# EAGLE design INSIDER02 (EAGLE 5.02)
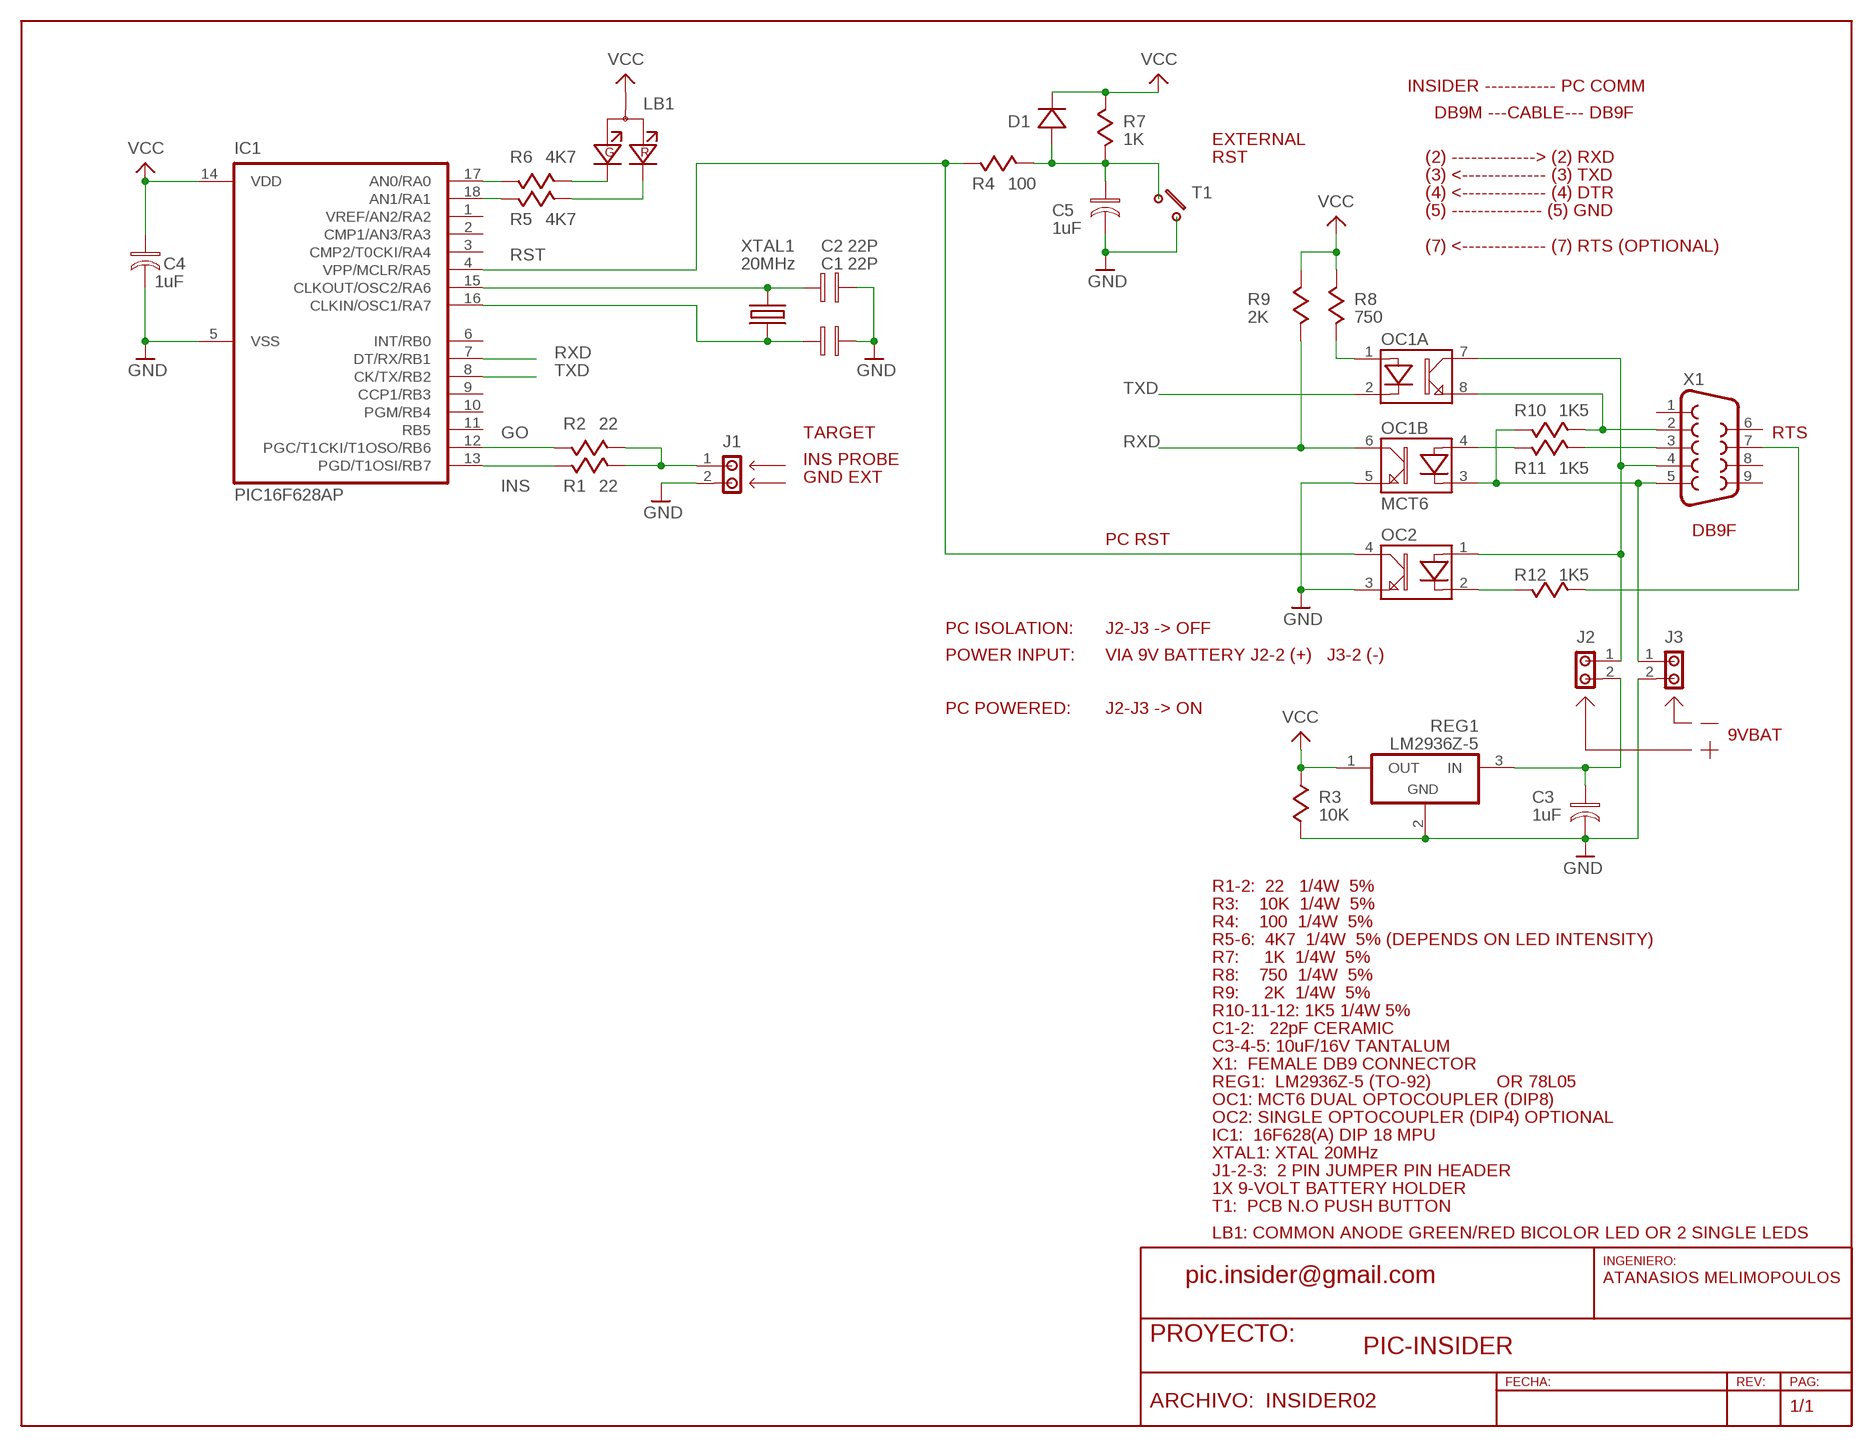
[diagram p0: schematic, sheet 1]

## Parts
C1  22P  CAP02  [C02]
C2  22P  CAP02  [C02]
C3  1uF  CAPE01  [CP01]
C4  1uF  CAPE01  [CP01]
C5  1uF  CAPE01  [CP01]
D1  1N4148  DIODE03  [D03]
IC1  PIC16F628AP  [DIL18]
J1  JMP2  [JP2]
J2  JMP2  [JP2]
J3  JMP2  [JP2]
LB1  LEDBIAC  [LEDBAC]
OC1  MCT6  OPTO2G  [DIL08]
OC2  OPTO1A  [DIL04]
R1  22  RES03  [R03]
R2  22  RES03  [R03]
R3  10K  RES03  [R03]
R4  100  RES03  [R03]
R5  4K7  RES03  [R03]
R6  4K7  RES03  [R03]
R7  1K  RES03  [R03]
R8  750  RES03  [R03]
R9  2K  RES03  [R03]
R10  1K5  RES03  [R03]
R11  1K5  RES03  [R03]
R12  1K5  RES03  [R03]
REG1  LM2936Z-5  78XXL  [TO92A]
T1  TEC3  [TEC3L]
X1  F09D  [F09D]
XTAL1  20MHz  XTALV300  [HC49V]

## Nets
GND: C1.P$2 C2.P$2 C3.P$2 C4.P$2 C5.P$2 IC1.5(VSS) J1.2 J3.2 OC1.5(B:E) OC2.3(E) R3.P$2 REG1.2(GND) T1.1
GO: IC1.12(PGC/T1CKI/T1OSO/RB6) R2.P$2
INS: IC1.13(PGD/T1OSI/RB7) R1.P$1
N$1: J3.1 OC1.3(B:K) R10.P$1 X1.5
N$2: OC1.8(A:E) R10.P$2 X1.2
N$3: J2.1 OC1.7(A:C) OC2.1(A) X1.4
N$4: R11.P$2 X1.3
N$5: OC1.4(B:A) R11.P$1
N$6: OC1.1(A:A) R8.P$2
N$8: OC2.2(K) R12.P$1
N$9: J1.1 R1.P$2 R2.P$1
N$10: C2.P$1 IC1.15(CLKOUT/OSC2/RA6) XTAL1.1
N$11: C1.P$1 IC1.16(CLKIN/OSC1/RA7) XTAL1.2
N$12: IC1.17(AN0/RA0) R6.P$2
N$14: LB1.G(K2) R6.P$1
N$15: LB1.R(K1) R5.P$1
N$16: IC1.18(AN1/RA1) R5.P$2
N$18: R12.P$2 X1.7
N$19: C5.P$1 D1.P$1(A) R4.P$1 R7.P$2 T1.4
N$20: C3.P$1 J2.2 REG1.3(IN)
RST: IC1.4(VPP/MCLR/RA5) OC2.4(C) R4.P$2
RXD: IC1.7(DT/RX/RB1) OC1.6(B:C) R9.P$2
TXD: IC1.8(CK/TX/RB2) OC1.2(A:K)
VCC: C4.P$1 D1.P$2(K) IC1.14(VDD) LB1.A R3.P$1 R7.P$1 R8.P$1 R9.P$1 REG1.1(OUT)
Unconnected: IC1.1(VREF/AN2/RA2) IC1.2(CMP1/AN3/RA3) IC1.3(CMP2/T0CKI/RA4) IC1.6(INT/RB0) IC1.9(CCP1/RB3) IC1.10(PGM/RB4) IC1.11(RB5) X1.1 X1.6 X1.8 X1.9

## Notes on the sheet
- INSIDER ----------- PC COMM
- DB9M ---CABLE--- DB9F
- EXTERNAL
- RST | (2) -------------> (2) RXD
- (3) <------------- (3) TXD
- (4) <------------- (4) DTR
- (5) -------------- (5) GND
- (7) <------------- (7) RTS (OPTIONAL)
- TARGET | RTS
- INS PROBE
- GND EXT
- DB9F
- PC RST
- PC ISOLATION: | J2-J3 -> OFF
- POWER INPUT: | VIA 9V BATTERY J2-2 (+)   J3-2 (-)
- PC POWERED: | J2-J3 -> ON
- 9VBAT
- R1-2:  22   1/4W  5%
- R3:    10K  1/4W  5%
- R4:    100  1/4W  5%
- R5-6:  4K7  1/4W  5% (DEPENDS ON LED INTENSITY)
- R7:     1K  1/4W  5%
- R8:    750  1/4W  5%
- R9:     2K  1/4W  5%
- R10-11-12: 1K5 1/4W 5%
- C1-2:   22pF CERAMIC
- C3-4-5: 10uF/16V TANTALUM
- X1:  FEMALE DB9 CONNECTOR
- REG1:  LM2936Z-5 (TO-92) | OR 78L05
- OC1: MCT6 DUAL OPTOCOUPLER (DIP8)
- OC2: SINGLE OPTOCOUPLER (DIP4) OPTIONAL
- IC1:  16F628(A) DIP 18 MPU
- XTAL1: XTAL 20MHz
- J1-2-3:  2 PIN JUMPER PIN HEADER
- 1X 9-VOLT BATTERY HOLDER
- T1:  PCB N.O PUSH BUTTON
- LB1: COMMON ANODE GREEN/RED BICOLOR LED OR 2 SINGLE LEDS
- pic.insider@gmail.com | ATANASIOS MELIMOPOULOS
- PIC-INSIDER

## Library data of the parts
C1 C2 = AtaLib:CAP: Capacitor
C3-C5 = AtaLib:CAPE: Capacitor Pol. Elect.
D1 = AtaLib:DIODE: DIODES
IC1 = AtaLib:PIC16F6*: PIC 16F627 - 628 - 648 family
J1-J3 = AtaLib:JMP2: Jumper 2xPin
LB1 = AtaLib:LEDBIAC: LED BIcolor AC 5mm
OC1 = AtaLib:OPTO2G: OPTOCOUPLER dual unit
OC2 = AtaLib:OPTO1A: OPTOCOUPLER simple
R1-R12 = AtaLib:RES: Resistor
REG1 = AtaLib:78XX: Positive Voltage Regulator
T1 = AtaLib:TEC: TECLAS INDIVIDUALES
X1 = AtaLib:F09: D-SUB 9 FEMALE
XTAL1 = AtaLib:XTALV300: Xtal Vert 300 mils

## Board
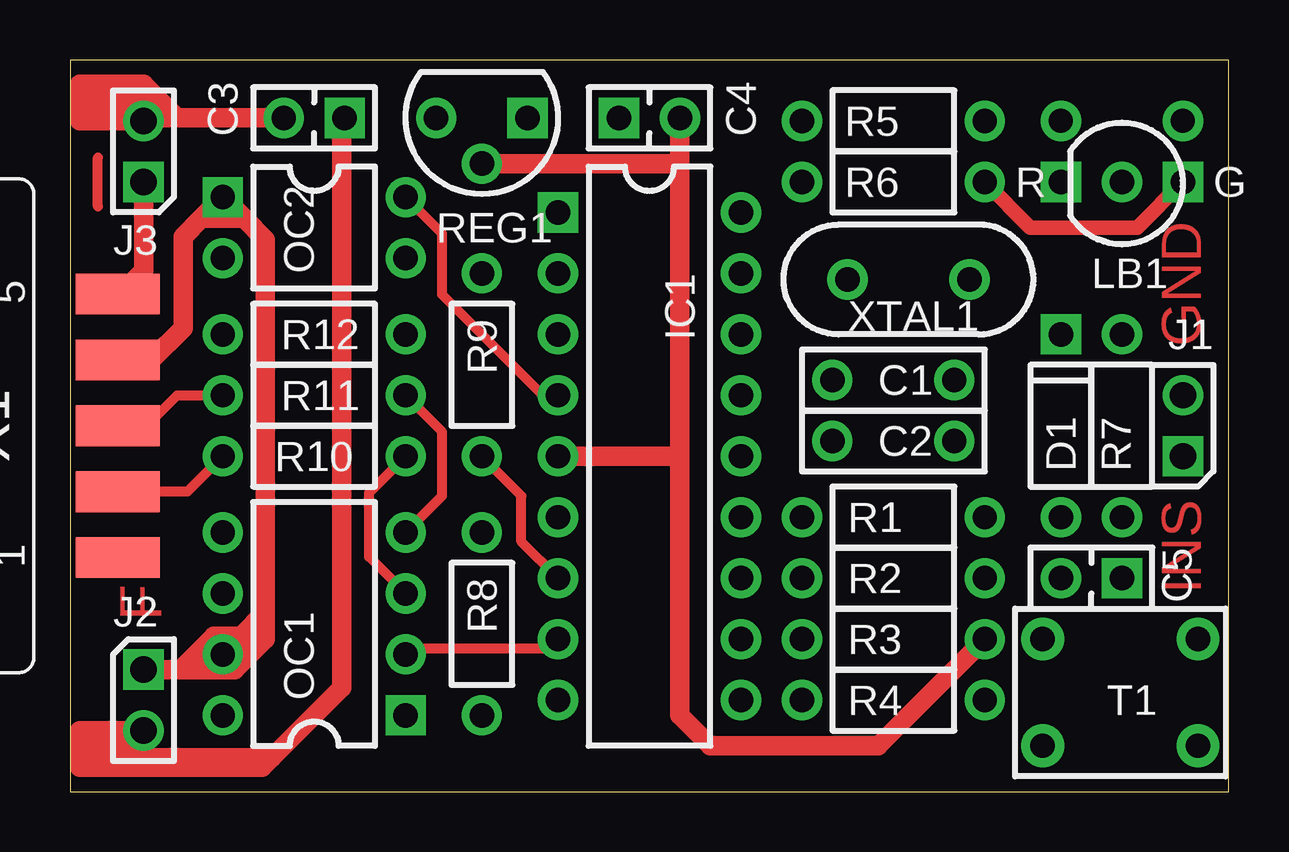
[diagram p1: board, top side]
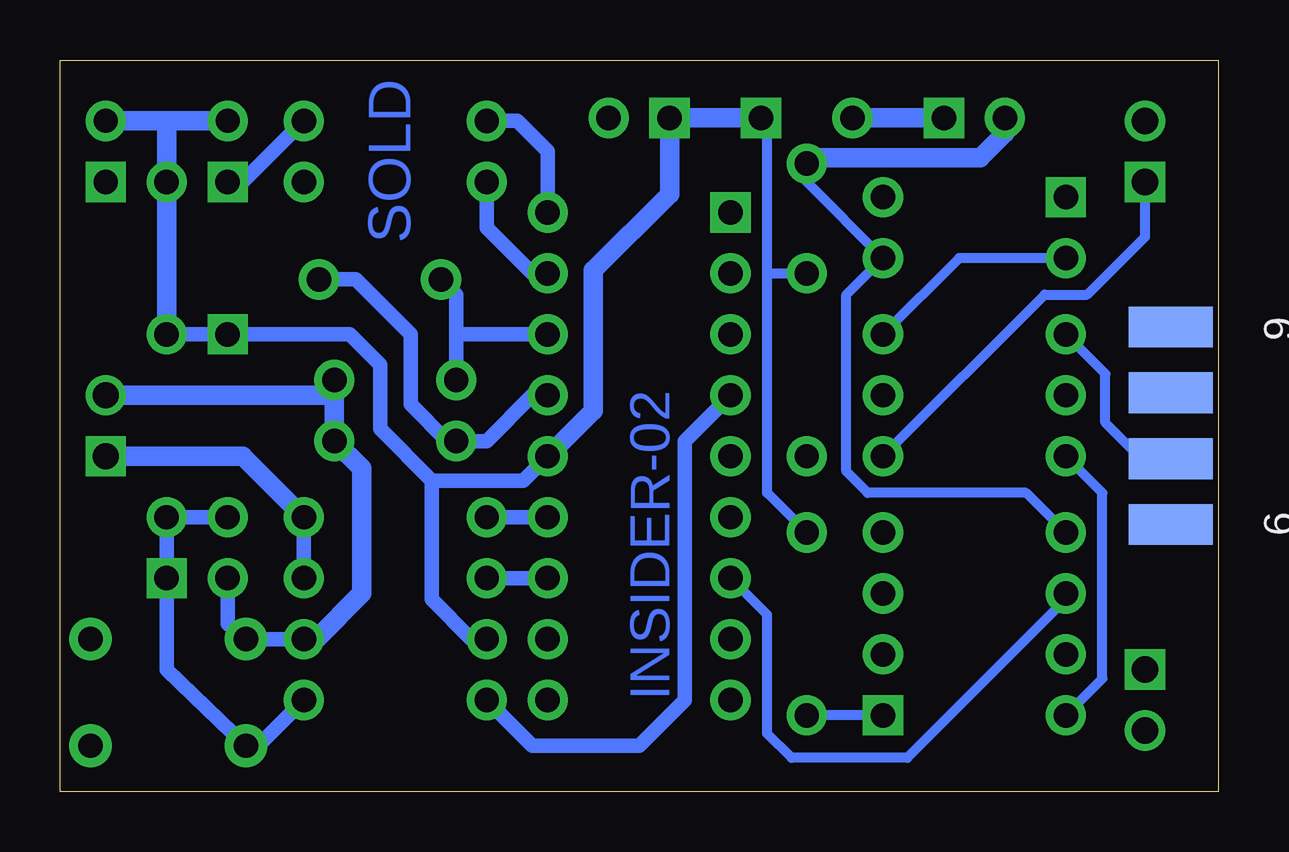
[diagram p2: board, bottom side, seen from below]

Size 48.26 x 30.48 mm. Coordinates in mm from the lower left corner, seen from the top.
Outline: 0,0 48.26,0 48.26,30.48 0,30.48 0,0
Copper layers (1*16): Top 0.035mm / dielectric 1.5mm / Bottom 0.035mm
Design rules "default": minimum track width 10mil, minimum drill 24mil, track to track 10mil, track to pad 10mil, pad to pad 10mil, via to via 10mil, smd to smd 8mil, copper to edge 25mil, drill to drill 10mil, minimum pad ring 10mil, minimum via ring 8mil, stop-mask expansion 8mil, vias tented up to drill 28mil, thermal gap 10mil

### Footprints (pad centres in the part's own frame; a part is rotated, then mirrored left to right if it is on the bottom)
C02 = drill 1.016 pad 1.676 round: P$1 -2.54,0; P$2 2.54,0
CP01 = drill 1.016 pad 1.676 square: P$1 -1.27,0 | drill 1.016 pad 1.676 round: P$2 1.27,0
D03 = drill 1.016 pad 1.676 round: P$1 -3.81,0 | drill 1.016 pad 1.676 square: P$2 3.81,0
DIL18 = drill 1.016 pad 1.676 square: 1 -10.16,-3.81 | drill 1.016 pad 1.676 round: 2 -7.62,-3.81; 3 -5.08,-3.81; 4 -2.54,-3.81; 5 0,-3.81; 6 2.54,-3.81; 7 5.08,-3.81; 8 7.62,-3.81; 9 10.16,-3.81; 10 10.16,3.81; 11 7.62,3.81; 12 5.08,3.81; 13 2.54,3.81; 14 0,3.81; 15 -2.54,3.81; 16 -5.08,3.81; 17 -7.62,3.81; 18 -10.16,3.81
JP2 = drill 1.1 pad 1.676 square: 1 0,1.27 | drill 1.1 pad 1.676 round: 2 0,-1.27
LEDBAC = drill 1.016 pad 1.676 round: A 0,0 | drill 1.016 pad 1.676 square: G 2.54,0; R -2.54,0
DIL08 = drill 1.016 pad 1.676 square: 1 -3.81,-3.81 | drill 1.016 pad 1.676 round: 2 -1.27,-3.81; 3 1.27,-3.81; 4 3.81,-3.81; 5 3.81,3.81; 6 1.27,3.81; 7 -1.27,3.81; 8 -3.81,3.81
DIL04 = drill 1.016 pad 1.676 square: 1 -1.27,-3.81 | drill 1.016 pad 1.676 round: 2 1.27,-3.81; 3 1.27,3.81; 4 -1.27,3.81
R03 = drill 1.016 pad 1.676 round: P$1 -3.81,0; P$2 3.81,0
TO92A = drill 1.016 pad 1.676 square: 1 -1.27,0 | drill 1.016 pad 1.676 round: 2 0.635,1.905; 3 2.54,0
TEC3L = drill 1.016 pad 1.778 round: 1 -2.667,2.54; 2 3.81,2.54; 3 3.81,-1.905; 4 -2.667,-1.905
F09D = smd 1.7 x 3.5: 1 -5.486,-6.045; 2 -2.743,-6.045; 3 0,-6.045; 4 2.743,-6.045; 5 5.486,-6.045 | smd 1.7 x 3.5 bottom: 6 -4.115,-6.045; 7 -1.372,-6.045; 8 1.372,-6.045; 9 4.115,-6.045
HC49V = drill 1.016 pad 1.676 round: 1 -2.54,0; 2 2.54,0

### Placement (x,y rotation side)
C1  34.29,17.14 0 top
C2  34.29,14.61 0 top
C3  10.16,28.07 180 top
C4  24.13,28.07 0 top
C5  42.55,8.89 180 top
D1  41.27,15.24 90 top
IC1  24.13,13.97 270 top
J1  46.35,15.24 180 top
J2  3.05,3.81 0 top
J3  3.05,26.67 180 top
LB1  43.81,25.4 0 top
OC1  10.16,6.99 90 top
OC2  10.16,23.5 270 top
R1  34.29,11.43 0 top
R2  34.29,8.89 180 top
R3  34.29,6.35 0 top
R4  34.29,3.81 180 top
R5  34.29,27.94 180 top
R6  34.29,25.4 180 top
R7  43.81,15.24 270 top
R8  17.14,6.99 270 top
R9  17.14,17.78 270 top
R10  10.16,13.97 180 top
R11  10.16,16.51 180 top
R12  10.16,19.05 180 top
REG1  17.78,28.07 180 top
T1  43.18,3.81 0 top
X1  -4.06,15.24 90 top
XTAL1  34.92,21.34 180 top

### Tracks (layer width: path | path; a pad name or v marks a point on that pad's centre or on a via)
GND
  Top 0.813: 25.4,26.16 25.4,13.97 | 25.4,26.16 C4.P$2 | 25.4,13.97 25.4,3.17 26.67,1.91 33.66,1.91 R3.P$2 | 25.4,13.97 IC1.5 | 0.38,28.7 0.38,27.94 J3.2 3.05,28.07 | 0.38,28.7 0.38,29.46 3.05,29.46 | 3.05,29.46 3.05,28.7 | 3.05,28.07 3.05,28.7 | 3.05,28.7 0.38,28.7 | 3.05,28.07 3.05,29.46 | REG1.2 25.4,26.16 | C3.P$2 4.45,28.07 | 4.45,28.07 3.05,28.07 | 4.45,28.07 3.05,29.46
  Bottom 0.406: REG1.2 17.14,25.4 OC2.3 15.49,20.7 15.49,13.34 14.61,12.45 8,12.45 OC1.5
  Bottom 0.61: R3.P$2 T1.1 41.27,6.99 C5.P$2
  Bottom 0.813: 36.83,16.51 C2.P$2 35.69,13.46 35.69,8.26 37.59,6.35 R3.P$2 | 36.83,16.51 C1.P$2 | REG1.2 16.89,26.42 9.91,26.42 8.89,27.43 C3.P$2 | 36.83,16.51 J1.2
GO
  Bottom 0.61: IC1.12 R2.P$2
INS
  Bottom 0.61: IC1.13 R1.P$1
N$1
  Top 0.406: OC1.3 12.45,9.78 12.45,12.45 R10.P$1
  Top 0.813: J3.1 3.05,21.72 2.06,20.73 X1.5
  Bottom 0.406: J3.1 3.05,23.11 5.46,20.7 7.24,20.7 R10.P$1
N$2
  Top 0.406: X1.2 4.88,12.5 R10.P$2
  Bottom 0.406: OC1.8 4.83,4.7 4.83,12.45 R10.P$2
N$3
  Top 0.813: J2.1 4.57,5.08 | 4.57,5.08 5.71,5.08 | 5.71,5.08 OC1.7 7.11,6.48 | 7.11,6.48 8.13,7.49 | X1.4 3.38,17.98 4.7,19.3 4.7,23.11 5.46,23.88 | 8.13,7.49 8.13,22.99 7.24,23.88 | 7.24,23.88 OC2.1 5.46,23.88 | 7.24,23.88 5.46,23.88 | 5.71,5.08 6.86,5.08 8.13,6.35 8.13,7.49 | 7.11,6.48 5.97,6.48 4.57,5.08
N$4
  Top 0.406: X1.3 3.17,15.24 4.45,16.51 R11.P$2
N$5
  Top 0.406: OC1.4 15.49,12.32 15.49,14.99 R11.P$1
N$6
  Bottom 0.406: OC1.1 R8.P$2
N$7
  Top 0.406: 1.14,24.38 1.14,26.42
N$8
  Bottom 0.406: OC2.2 10.79,22.23 R12.P$1
N$9
  Bottom 0.61: R2.P$1 R1.P$2
  Bottom 0.813: R1.P$2 40.64,13.97 J1.1
N$10
  Bottom 0.61: IC1.15 28.57,16.51 30.48,14.61 C2.P$1 32.13,14.61 33.66,16.13 33.66,19.05 35.94,21.34 XTAL1.1
N$11
  Bottom 0.61: C1.P$1 31.75,19.05 | 31.75,19.05 31.75,20.7 XTAL1.2 | 31.75,19.05 IC1.16
N$12
  Bottom 0.61: IC1.17 28.57,21.59 30.48,23.5 R6.P$2
N$14
  Top 0.61: R6.P$1 40.01,23.5 44.45,23.5 LB1.G
N$15
  Bottom 0.61: LB1.R 40.64,25.4 R5.P$1
N$16
  Bottom 0.61: IC1.18 27.94,26.67 29.21,27.94 R5.P$2
N$17  (via drill 1 pad 1.68)
  Bottom 0.813: v41.27,27.94 v46.35,27.94
N$18
  Bottom 0.406: X1.7 3.2,13.87 4.7,15.37 4.7,17.4 R12.P$2
N$19
  Bottom 0.61: D1.P$1 R7.P$2 C5.P$1 43.81,5.08 T1.4 40.01,1.91 R4.P$1
N$20
  Top 0.61: J2.2 3.05,1.52
  Top 0.813: 3.05,1.78 J2.2 | 3.05,1.78 3.05,1.52 3.05,1.4 | 3.05,1.4 3.05,1.02 2.92,1.02 | 2.92,1.02 0.38,1.02 0.38,1.78 | 0.38,1.78 0.38,2.54 J2.2 | 0.38,1.78 3.05,1.78 | J2.2 3.05,1.4 | 3.05,1.4 8.38,1.4 | 8.38,1.4 11.3,4.32 11.3,27.94 C3.P$1 | 2.92,1.02 8,1.02 8.38,1.4
  Bottom 0.813: C3.P$1 REG1.3
RST
  Top 0.406: OC2.4 15.49,23.24 15.49,20.7 19.68,16.51 IC1.4
  Bottom 0.61: IC1.4 22.23,14.61 22.23,3.81 24.13,1.91 28.57,1.91 R4.P$2
RXD
  Top 0.406: R9.P$2 18.8,12.32 18.8,10.41 IC1.7
  Bottom 0.406: OC1.6 6.35,8 12.95,1.4 17.78,1.4 18.8,2.41 18.8,7.37 IC1.7
TXD
  Top 0.406: OC1.2 14.22,5.97 19.94,5.97 IC1.8
VCC
  Bottom 0.406: 18.8,21.59 18.8,12.45 R8.P$1 | 18.8,21.59 18.8,27.81 REG1.1 | 18.8,21.59 R9.P$1
  Bottom 0.61: 32.77,12.95 32.77,8 31.11,6.35 R3.P$1 | 32.77,12.95 28.96,12.95 IC1.14 | R7.P$1 D1.P$2 36.2,19.05 34.92,17.78 34.92,15.11 32.77,12.95
  Bottom 0.813: 43.81,27.94 LB1.A R7.P$1 | IC1.14 26.04,15.88 26.04,21.72 22.86,24.89 C4.P$1 REG1.1

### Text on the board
Top: GND | INS | F
Bottom: SOLD | INSIDER-02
